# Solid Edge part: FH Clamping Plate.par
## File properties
Author: Dan
Template: metric part.par
Last saved by: Dan
Revision: 25
Application: Solid Edge
Density: 7833.000 kg/m^3
Accuracy: 0.990
Material: Steel
Face Style: Steel
Fill Style: ANSI32(Steel)
Virtual Style: Machined steel
Coef. of Thermal Exp: 1.3e-05
Thermal Conductivity: 32.0
Specific Heat: 481.0
Modulus of Elasticity: 199947953000.0
Poisson's Ratio: 0.29
Yield Stress: 262000766.0
Ultimate Stress: 358527364.0
Elongation: 0.0
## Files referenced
..\Fixed Half.asm
C:\Drawing Files Other\Dave\Tente\HUP 125X36H45-TSA 02-07-2011\Wheel Mould\Stripper Plate.par
YC:\Drawing Files Other\Dave\Tente\HUP 125X36H45-TSA 02-07-2011\Wheel Mould\Fixed Half.asm
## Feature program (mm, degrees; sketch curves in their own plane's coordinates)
sketch for "unnamed Protrusion 1" plane through (0, 0, 0) normal (0, 0, 1) x-axis (1, 0, 0)
extrude "unnamed Protrusion 1" add finite 26 along -normal
sketch for "Hole_13" plane through (0, 0, -26) normal (0, 0, -1) x-axis (1, 0, 0)
hole "Hole_13" diameter 60 through  VBottomAngle = 118 deg
sketch for "Hole_22" plane through (0, 0, -26) normal (0, 0, -1) x-axis (-1, 0, 0)
hole "Hole_22" diameter 12 through  CounterBoreDepth = 20 mm; VBottomAngle = 118 deg
sketch for "unnamed Hole 1" plane through (0, 0, -26) normal (0, 0, -1) x-axis (-1, 0, 0)
hole "unnamed Hole 1" through
sketch for "unnamed Hole 2" plane through (0, 0, -26) normal (0, 0, -1) x-axis (-1, 0, 0)
  hole centre (120, 170) bore radius 6
hole "unnamed Hole 2" through
sketch for "unnamed Hole 3" plane through (0, 0, -26) normal (0, 0, -1) x-axis (-1, 0, 0)
  hole centre (-120, -170) bore radius 6
hole "unnamed Hole 3" through
pattern "unnamed Pattern 1" of "Hole_22", "unnamed Hole 1", "unnamed Hole 2", "unnamed Hole 3"
sketch for "Hole_26" plane through (0, 0, -26) normal (0, 0, -1) x-axis (-1, 0, 0)
  hole centre (-109.2946, 109.2947) bore radius 2.5
hole "Hole_26" diameter 5 through  CounterBoreDepth = 23 mm; VBottomAngle = 118 deg
sketch for "unnamed Hole 4" plane through (0, 0, -26) normal (0, 0, -1) x-axis (-1, 0, 0)
  hole centre (-95.5061, 95.5061) bore radius 2.5
hole "unnamed Hole 4" through
sketch for "unnamed Hole 5" plane through (0, 0, -26) normal (0, 0, -1) x-axis (-1, 0, 0)
  hole centre (-54.4939, 95.5061) bore radius 2.5
hole "unnamed Hole 5" through
sketch for "unnamed Hole 6" plane through (0, 0, -26) normal (0, 0, -1) x-axis (-1, 0, 0)
  hole centre (-40.7053, 109.2946) bore radius 2.5
hole "unnamed Hole 6" through
sketch for "unnamed Hole 7" plane through (0, 0, -26) normal (0, 0, -1) x-axis (-1, 0, 0)
  hole centre (-54.4939, 54.4939) bore radius 2.5
hole "unnamed Hole 7" through
sketch for "unnamed Hole 8" plane through (0, 0, -26) normal (0, 0, -1) x-axis (-1, 0, 0)
  hole centre (-40.7054, 40.7053) bore radius 2.5
hole "unnamed Hole 8" through
sketch for "unnamed Hole 9" plane through (0, 0, -26) normal (0, 0, -1) x-axis (-1, 0, 0)
  hole centre (-95.5061, 54.4939) bore radius 2.5
hole "unnamed Hole 9" through
sketch for "unnamed Hole 10" plane through (0, 0, -26) normal (0, 0, -1) x-axis (-1, 0, 0)
  hole centre (-109.2947, 40.7054) bore radius 2.5
hole "unnamed Hole 10" through
pattern "unnamed Pattern 2" of "Hole_26", "unnamed Hole 4", "unnamed Hole 5", "unnamed Hole 6", "unnamed Hole 7", "unnamed Hole 8", "unnamed Hole 9", "unnamed Hole 10"
sketch for "Hole_34" plane through (0, 0, -26) normal (0, 0, -1) x-axis (-1, 0, 0)
  hole centre (-109.2946, 109.2947) bore radius 5.053
hole "Hole_34" nominal diameter 12 finite
sketch for "unnamed Hole 11" plane through (0, 0, -26) normal (0, 0, -1) x-axis (-1, 0, 0)
  hole centre (-54.4939, 95.5061) bore radius 5.053
hole "unnamed Hole 11" finite
sketch for "unnamed Hole 12" plane through (0, 0, -26) normal (0, 0, -1) x-axis (-1, 0, 0)
  hole centre (-40.7053, 109.2946) bore radius 5.053
hole "unnamed Hole 12" finite
sketch for "unnamed Hole 13" plane through (0, 0, -26) normal (0, 0, -1) x-axis (-1, 0, 0)
  hole centre (-54.4939, 54.4939) bore radius 5.053
hole "unnamed Hole 13" finite
sketch for "unnamed Hole 14" plane through (0, 0, -26) normal (0, 0, -1) x-axis (-1, 0, 0)
  hole centre (-40.7054, 40.7053) bore radius 5.053
hole "unnamed Hole 14" finite
sketch for "unnamed Hole 15" plane through (0, 0, -26) normal (0, 0, -1) x-axis (-1, 0, 0)
  hole centre (-95.5061, 54.4939) bore radius 5.053
hole "unnamed Hole 15" finite
sketch for "unnamed Hole 16" plane through (0, 0, -26) normal (0, 0, -1) x-axis (-1, 0, 0)
  hole centre (-109.2947, 40.7054) bore radius 5.053
hole "unnamed Hole 16" finite
sketch for "unnamed Hole 17" plane through (0, 0, -26) normal (0, 0, -1) x-axis (-1, 0, 0)
  hole centre (-95.5061, 95.5061) bore radius 5.053
hole "unnamed Hole 17" finite
pattern "unnamed Pattern 3" of "Hole_34", "unnamed Hole 11", "unnamed Hole 12", "unnamed Hole 13", "unnamed Hole 14", "unnamed Hole 15", "unnamed Hole 16", "unnamed Hole 17"
mirror "unnamed Mirror 1" of "unnamed Pattern 2", "unnamed Pattern 3"
pattern "unnamed Pattern 4"
mirror "unnamed Mirror 2" of "unnamed Pattern 2", "unnamed Pattern 4", "unnamed Pattern 3"
pattern "unnamed Pattern 5"
sketch for "unnamed Cutout 1" plane through (0, 0, 0) normal (0, 0, 1) x-axis (1, 0, 0)
  circle centre (0, 0) radius 40
extrude "unnamed Cutout 1" cut through along -normal
sketch for "ExtrudedCutout_3" plane through (0, 0, -26) normal (0, 0, -1) x-axis (1, 0, 0)
extrude "ExtrudedCutout_3" cut finite 5 along -normal
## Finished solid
Body 1: solid body, 184 faces, 242 edges, 24 vertices.
  Faces by surface: cylinder 109, plane 75
  Edges by curve: circle 222, line 20
Bounding box of the edges (mm): 446.000 x 396.000 x 26.000, from (-223, -198, -26) to (223, 198, 0).
Cylindrical faces by radius (mm): R2.5 x32, R5 x32, R5.053 x32, R6 x4, R10 x4, R40 x1, R80 x4
Planar faces by outward normal: +x 1, +y 1, +z 1, -x 1, -y 1, -z 70
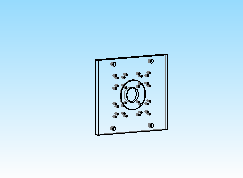
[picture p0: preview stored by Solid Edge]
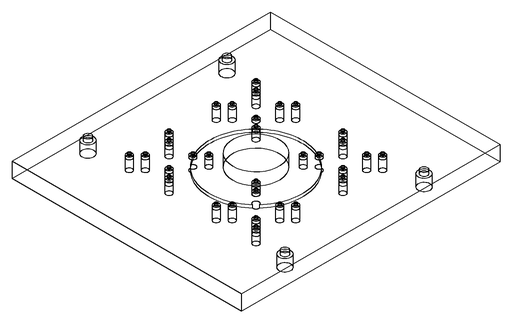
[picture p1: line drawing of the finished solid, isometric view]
